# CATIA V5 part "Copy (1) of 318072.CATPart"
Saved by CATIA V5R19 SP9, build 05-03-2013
Part number: Copy (1) of 318072
Source: Unknown
Bounding box of the stored display mesh (mm): x -164.771 to -4.52, y -231.182 to -196.661, z 470.762 to 488.942
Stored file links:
  D:\16-SIL\kale oto\R19_V1\Copy (1) of 318072.CATPart
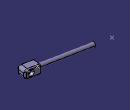
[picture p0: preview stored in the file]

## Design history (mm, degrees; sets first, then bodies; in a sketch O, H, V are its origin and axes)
Set1
  Point1 to Point3: stored without definition
Body1 "241\\233\\232\\MANIFOLD_SOLID_BREP #159996" (main body)
  Solid1: solid without history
